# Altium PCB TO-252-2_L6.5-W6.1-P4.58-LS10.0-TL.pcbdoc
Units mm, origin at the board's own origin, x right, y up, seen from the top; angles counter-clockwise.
Board outline 24.3 x 19.8 mm, 2 copper layers (Top Layer, Bottom Layer), stack 0 mm thick; 1 components, 0 nets, 3 pads, 0 vias.
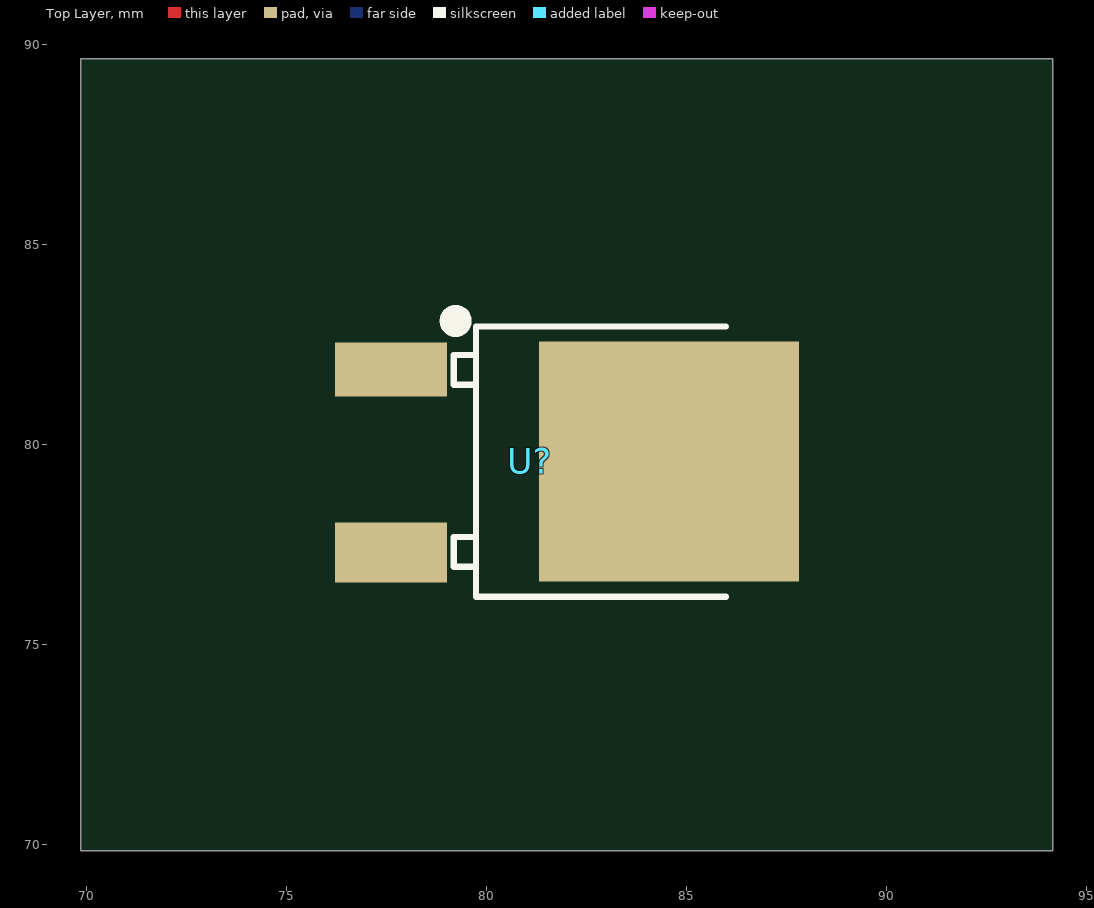
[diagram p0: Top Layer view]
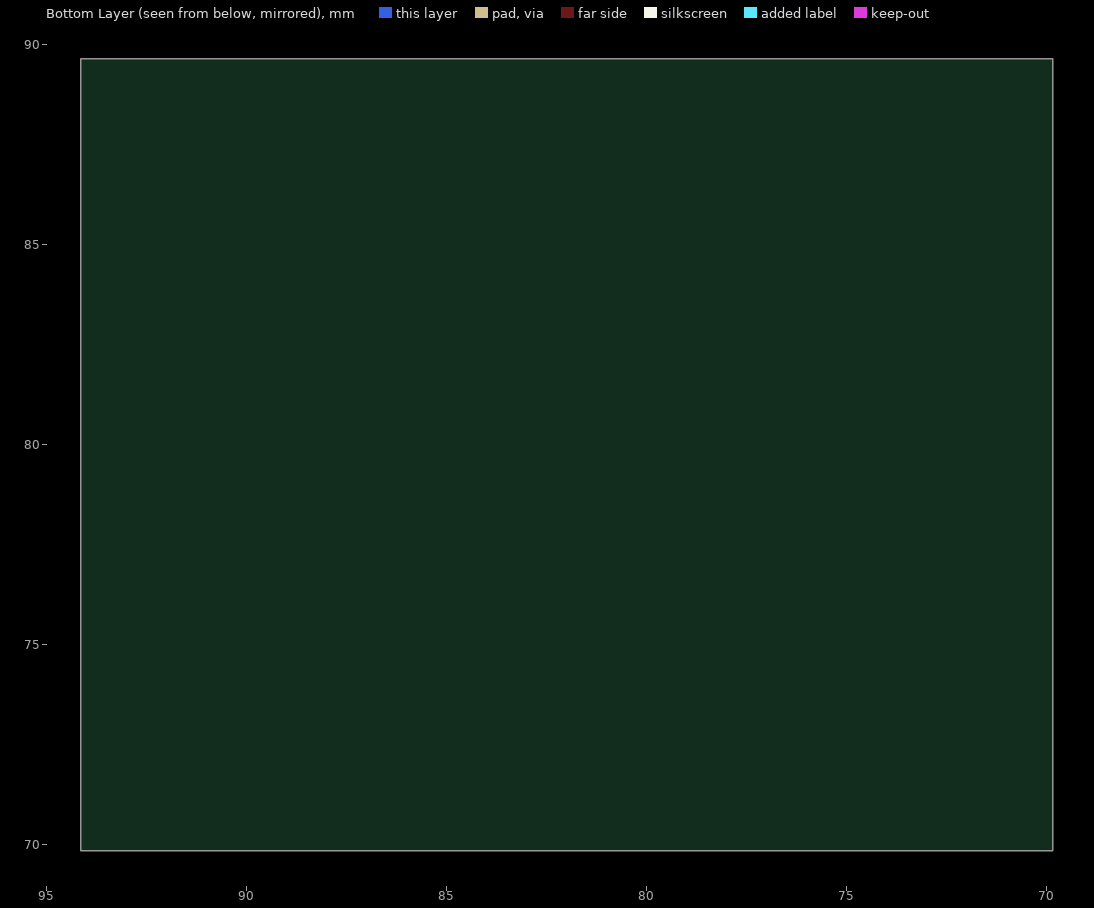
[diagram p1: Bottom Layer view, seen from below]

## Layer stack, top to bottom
Top Layer: signal copper (thickness not stored)
Bottom Layer: signal copper (thickness not stored)

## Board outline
94.15,69.85 69.85,69.85 69.85,89.645 94.15,89.645

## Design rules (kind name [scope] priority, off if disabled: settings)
PasteMaskExpansion "Paste Mask Expansion" [All] p1: expansion=0
SolderMaskExpansion "Solder Mask Expansion" [IsVia] p1: expansion=-25.4 istentingtop=TRUE
SolderMaskExpansion "Solder Mask Expansion" [All] p2: expansion=0.051 istentingtop=FALSE

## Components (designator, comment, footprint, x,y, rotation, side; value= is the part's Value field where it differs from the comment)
U? "" TO-252-2_L6.5-W6.1-P4.58-LS10.0-TL 81.075,79.593 r0 top

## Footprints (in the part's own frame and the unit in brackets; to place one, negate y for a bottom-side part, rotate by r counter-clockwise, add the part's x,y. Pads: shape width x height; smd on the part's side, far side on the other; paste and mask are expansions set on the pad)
TO-252-2_L6.5-W6.1-P4.58-LS10.0-TL [mm]
  rect 2.8x1.35 smd: 1(-3.475,2.29)
  rect 2.8x1.5 smd: 3(-3.475,-2.29)
  rect 6.5x6 smd: 4(3.475,-0.017)
  silkscreen extent -2.06,-3.39 4.9,3.7

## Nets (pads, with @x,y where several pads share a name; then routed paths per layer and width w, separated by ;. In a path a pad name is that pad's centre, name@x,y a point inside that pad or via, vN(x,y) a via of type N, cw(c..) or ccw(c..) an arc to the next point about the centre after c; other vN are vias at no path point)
pads on no net: U?.1 U?.3 U?.4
